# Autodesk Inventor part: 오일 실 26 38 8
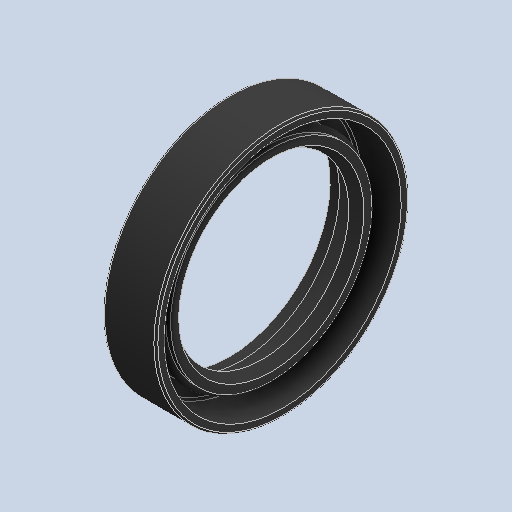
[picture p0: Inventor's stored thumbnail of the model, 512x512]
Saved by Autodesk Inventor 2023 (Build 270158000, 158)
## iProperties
Created: 2025-03
Part Number: 오일 실 26 38 8
Material: 고무
Description: 오일-실
Document SubType Name: Modeling
Designer: Admin
Density: 0.93 g/cm^3
Appearance: 기본값
Author: jhkim
Sending System: Autodesk Inventor 2025
Preprocessor: ST-DEVELOPER v20
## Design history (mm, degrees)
feature "Solid1"
node "솔리드1"
